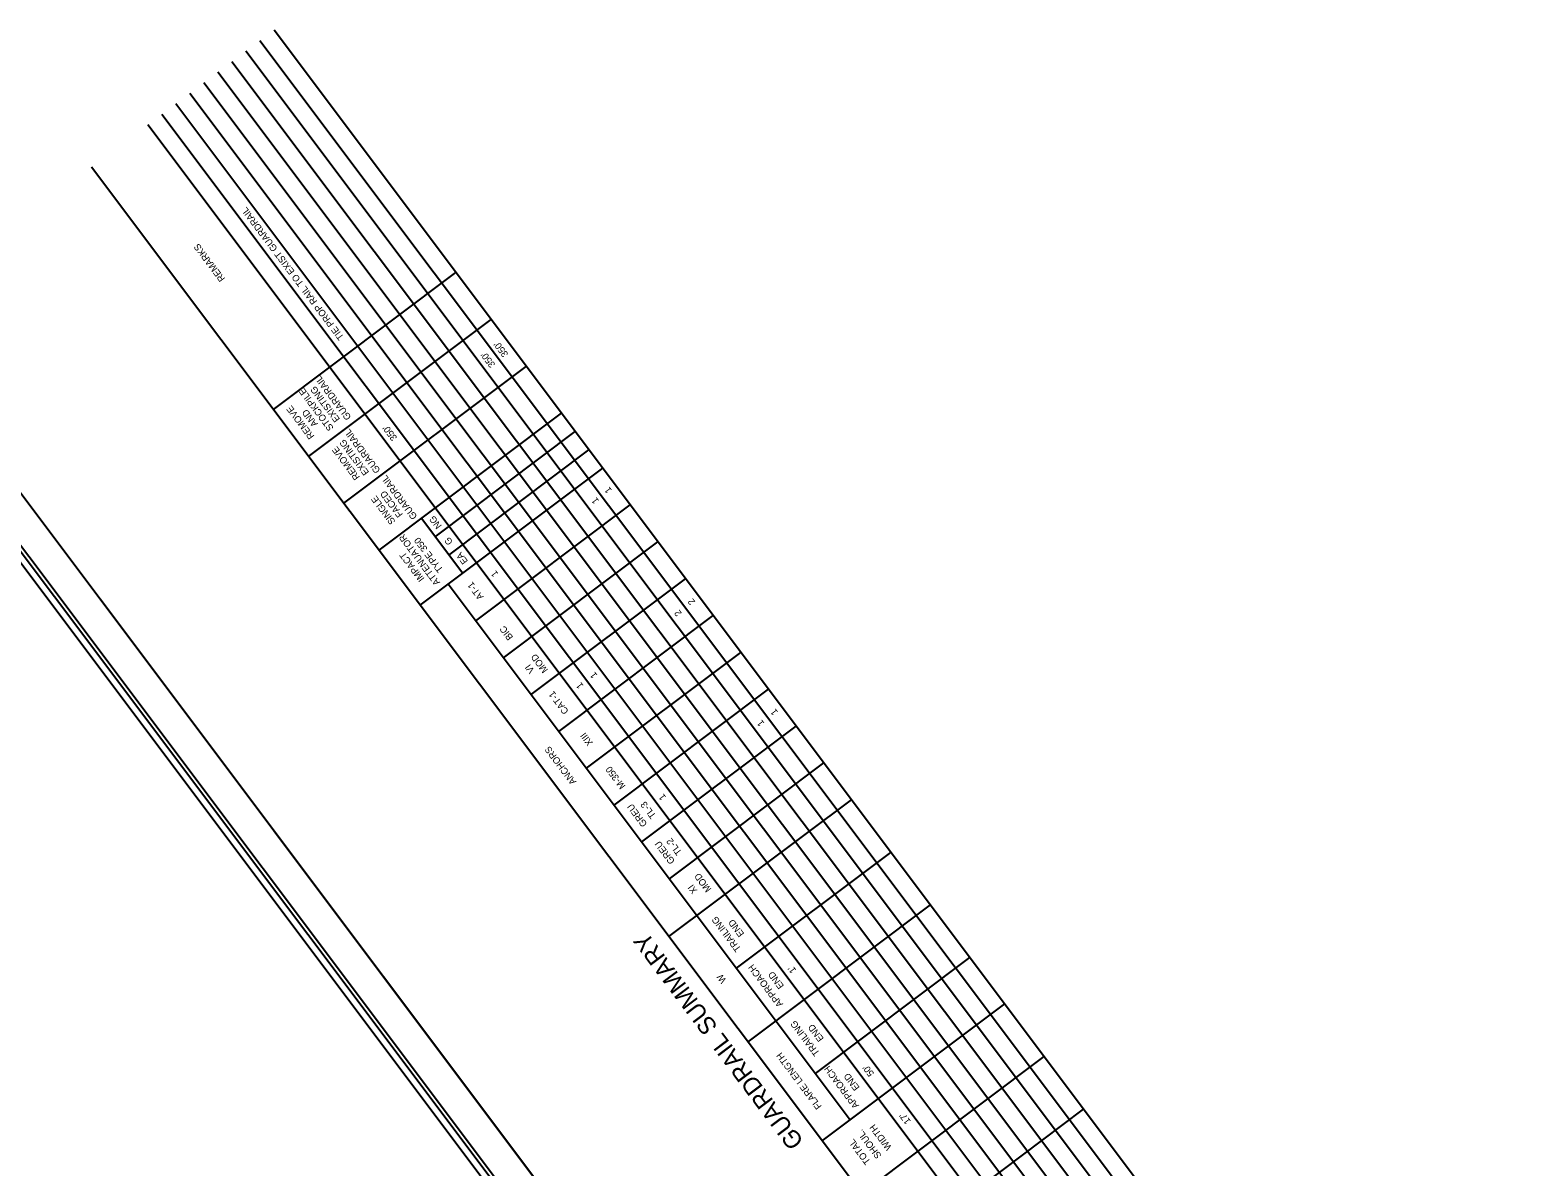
# Model space of a CAD drawing. Extents: x -35.4 to 7.5, y -22.3 to 27.3.
# Drawn here: x -14.76 to 6.73, y 11.08 to 27.28 of the extents above; entities that cross this region are included whole.
import ezdxf

# ---------------------------------------------------------------- set-up
doc = ezdxf.new("R2010")
doc.units = 0
for name, color, linetype in [('Default', 7, 'Continuous'), ('Sheet Cutting Line CELL', 7, 'Continuous'), ('Sheet Plot Border Inside CELL', 7, 'Continuous'), ('Sheet Plot Border Outside CELL', 7, 'Continuous'), ('Sheet Summary Combination CELL', 7, 'Continuous'), ('Sheet Summary Combination Grid CELL', 7, 'Continuous'), ('Typical Text Asphalt at Bridge Approach CELL', 7, 'Continuous')]:
    doc.layers.add(name, color=color, linetype=linetype)

msp = doc.modelspace()

# ---------------------------------------------------------------- linework, layer by layer
at = {"layer": 'Default'}
msp.add_lwpolyline([(-0.077, -0.055), (-18.097, 23.955), (-22.648, 20.539), (-4.628, -3.47)], close=True, dxfattribs=at)
at = {"layer": 'Sheet Cutting Line CELL'}
msp.add_line((2.405, -2.368), (-17.812, 24.569), dxfattribs=at)
at = {"layer": 'Sheet Plot Border Inside CELL'}
msp.add_lwpolyline([(-34.994, 11.561), (-14.987, -15.096), (1.89, -2.429), (-18.117, 24.228)], close=True, dxfattribs=at)
at = {"layer": 'Sheet Plot Border Outside CELL'}
msp.add_lwpolyline([(-35.408, 11.363), (-15.19, -15.574), (2.405, -2.368), (-17.812, 24.569)], close=True, dxfattribs=at)
at = {"layer": 'Sheet Summary Combination CELL'}
msp.add_lwpolyline([(-34.804, 11.392), (-16.795, -12.602), (0, 0.003), (-18.008, 23.997)], close=True, dxfattribs=at)
at = {"layer": 'Sheet Summary Combination Grid CELL'}
for p, q in [((6.527, 3.133), (-11.481, 27.126)), ((6.527, 3.133), (-11.481, 27.126)), ((6.727, 3.283), (-11.281, 27.276)), ((6.727, 3.283), (-11.281, 27.276)), ((6.327, 2.982), (-11.681, 26.976)), ((6.327, 2.982), (-11.681, 26.976)), ((5.927, 2.682), (-12.081, 26.676)), ((6.127, 2.832), (-11.881, 26.826)), ((5.727, 2.532), (-12.281, 26.526)), ((5.727, 2.532), (-12.281, 26.526)), ((5.327, 2.232), (-12.681, 26.226)), ((5.527, 2.382), (-12.481, 26.376)), ((5.527, 2.382), (-12.481, 26.376)), ((5.127, 2.082), (-12.881, 26.076)), ((4.927, 1.932), (-13.081, 25.926)), ((4.128, 1.332), (-13.881, 25.326)), ((-11.29, 21.874), (-8.691, 23.825)), ((-10.788, 21.205), (-8.189, 23.156)), ((-10.286, 20.536), (-7.687, 22.487)), ((-9.784, 19.868), (-7.185, 21.819)), ((-8.985, 20.061), (-6.99, 21.56)), ((-8.789, 19.799), (-6.794, 21.298)), ((-9.198, 19.086), (-6.598, 21.037)), ((-8.404, 18.862), (-6.205, 20.513)), ((-8.594, 19.54), (-9.177, 20.317)), ((-8.01, 18.337), (-5.811, 19.988)), ((-8.798, 19.387), (-3.07, 11.754)), ((-7.616, 17.812), (-5.417, 19.462)), ((-7.222, 17.287), (-5.023, 18.938)), ((-6.828, 16.762), (-4.629, 18.413)), ((-6.435, 16.238), (-4.235, 17.888)), ((-6.04, 15.712), (-3.841, 17.363)), ((-5.646, 15.188), (-3.447, 16.838)), ((-5.653, 14.363), (-3.053, 16.314)), ((-4.69, 13.913), (-2.49, 15.563)), ((-4.527, 12.863), (-1.928, 14.814)), ((-3.564, 12.413), (-1.365, 14.064)), ((-3.469, 11.454), (-0.87, 13.405)), ((-2.907, 10.705), (-0.308, 12.655)), ((-2.344, 9.954), (0.255, 11.905))]:
    msp.add_line(p, q, dxfattribs=at)
at = {"layer": 'Typical Text Asphalt at Bridge Approach CELL'}
msp.add_line((5.727, 2.532), (-12.281, 26.526), dxfattribs=at)

# ---------------------------------------------------------------- texts
at = {"layer": 'Sheet Summary Combination CELL'}
for s, height, p in [('TIE PROP RAIL TO EXIST GUARDRAIL', 0.096, (-10.279, 22.905)), ('REMARKS', 0.096, (-11.973, 23.737)), ("350'", 0.096, (-7.938, 22.663)), ("350'", 0.096, (-8.123, 22.513)), ('GUARDRAIL', 0.096, (-10.175, 21.765)), ('STOCKPILE', 0.096, (-10.426, 21.612)), ('EXISTING', 0.096, (-10.336, 21.736)), ('REMOVE', 0.096, (-10.701, 21.493)), ('AND', 0.096, (-10.651, 21.669)), ('GUARDRAIL', 0.096, (-9.76, 21.008)), ("350'", 0.096, (-9.521, 21.471)), ('REMOVE', 0.096, (-10.052, 20.911)), ('EXISTING', 0.096, (-9.921, 20.979)), ('GUARDRAIL', 0.096, (-9.234, 20.349)), ('SINGLE', 0.096, (-9.546, 20.278)), ('FACED', 0.096, (-9.439, 20.379)), ('1', 0.096, (-6.646, 20.572)), ('1', 0.096, (-6.462, 20.722)), ('NG', 0.096, (-8.887, 20.216)), ('ATTENUATOR', 0.096, (-8.909, 19.41)), ('TYPE 350', 0.096, (-8.865, 19.594)), ('G', 0.096, (-8.727, 19.985)), ('IMPACT', 0.096, (-9.132, 19.463)), ('EA', 0.096, (-8.513, 19.712)), ('1', 0.096, (-8.08, 19.531)), ('AT-1', 0.096, (-8.29, 19.205)), ('2', 0.096, (-5.274, 19.133)), ('2', 0.096, (-5.466, 18.97)), ('BIC', 0.096, (-7.869, 18.63)), ('MOD', 0.096, (-7.372, 18.163)), ('VI', 0.096, (-7.564, 18.156)), ('1', 0.096, (-6.669, 18.086)), ('CAT-1', 0.096, (-7.077, 17.575)), ('1', 0.096, (-6.866, 17.938)), ('1', 0.096, (-4.289, 17.402)), ('1', 0.096, (-4.096, 17.561)), ('XIII', 0.096, (-6.732, 17.127)), ('ANCHORS', 0.096, (-6.969, 16.571)), ('M-350', 0.096, (-6.268, 16.509)), ('1', 0.096, (-5.69, 16.35)), ('GREU', 0.096, (-5.957, 15.97)), ('TL-3', 0.096, (-5.832, 16.088)), ('GREU', 0.096, (-5.563, 15.44)), ('TL-2', 0.096, (-5.463, 15.566)), ('MOD', 0.096, (-5.044, 15.04)), ('XI', 0.096, (-5.243, 15.02)), ('TRAILING', 0.096, (-4.622, 14.19)), ('END', 0.096, (-4.576, 14.404)), ('GUARDRAIL SUMMARY', 0.25, (-3.722, 11.448)), ('APPROACH', 0.096, (-4.023, 13.403)), ('W', 0.096, (-4.83, 13.743)), ('END', 0.096, (-4.01, 13.662)), ("1'", 0.096, (-3.834, 13.884)), ('TRAILING', 0.096, (-3.5, 12.706)), ('END', 0.096, (-3.442, 12.911)), ('FLARE LENGTH', 0.096, (-3.472, 11.947)), ('APPROACH', 0.096, (-2.94, 11.958)), ("50'", 0.096, (-2.725, 12.415)), ('END', 0.096, (-2.932, 12.214)), ("17'", 0.096, (-2.202, 11.734)), ('SHOUL.', 0.096, (-2.62, 11.245)), ('WIDTH', 0.096, (-2.474, 11.363)), ('TOTAL', 0.096, (-2.775, 11.159))]:
    msp.add_text(s, height=height, rotation=126.8893, dxfattribs=at).set_placement(p)

doc.saveas('drawing.dxf')
